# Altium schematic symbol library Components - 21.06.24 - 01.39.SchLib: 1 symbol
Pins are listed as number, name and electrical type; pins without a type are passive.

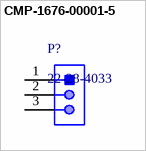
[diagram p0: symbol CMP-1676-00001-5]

## CMP-1676-00001-5
designator P?, comment 22-28-4033
Male Header, Pitch 2.54 mm, 1 x 3 Position, Height 8.38 mm, Tail Length 3.18 mm, RoHS, Bulk; Manufacturer: Molex; Rows: 1; Voltage Rating: 250 V; Current Rating: 4 A
footprint MOLX-22-28-4033_V (THD, 3-Leads, Body 7.62x2.49mm, Pitch 2.54mm)
pins: 1, 2, 3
